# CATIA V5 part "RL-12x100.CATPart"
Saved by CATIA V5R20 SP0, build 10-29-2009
Part number: _RL-12x100
Definition: NONE
Nomenclature: _RL-12x100
Source: Unknown
Description: PART-_RL-12x100-DESC
Bounding box of the stored display mesh (mm): x -100 to 12.5, y -7 to 7, z -7 to 7
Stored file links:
  C:\Users\Utente\Desktop\IO LAVORO\3D X SITO CF\X SITO\PLASTICA\RL\RL-12x100.CATPart
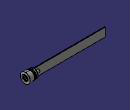
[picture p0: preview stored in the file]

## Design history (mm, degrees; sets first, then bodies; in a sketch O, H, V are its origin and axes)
Body1 "_RL-12x100" (main body)
  Solid1: solid without history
